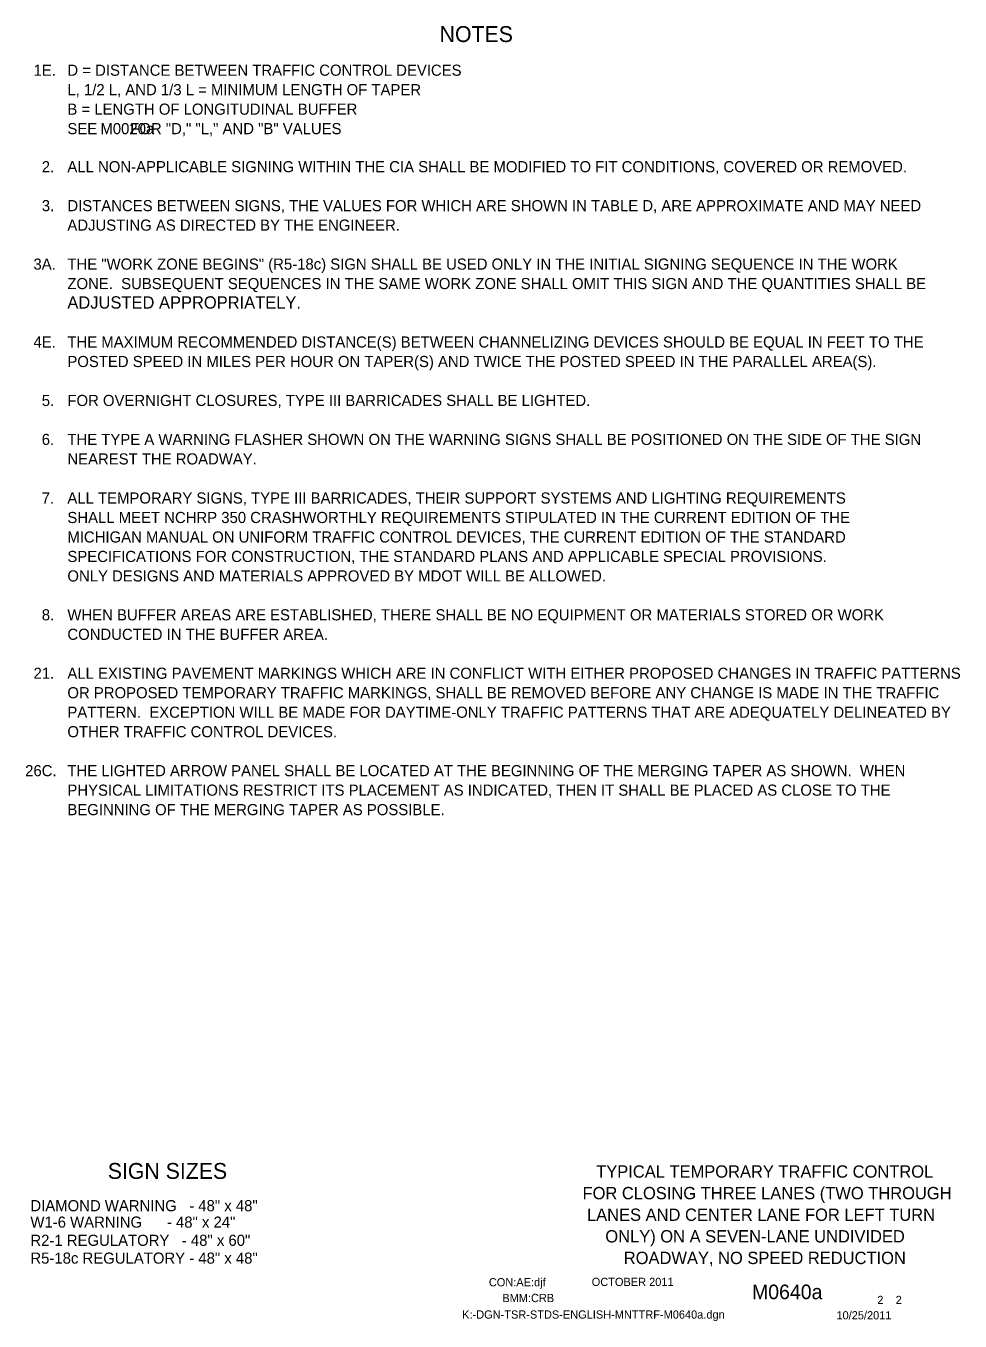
# Model space of a CAD drawing. Extents: x 16723 to 18475, y 7015 to 8267.
# Drawn here: x 17770 to 18475, y 7218 to 8195 of the extents above; entities that cross this region are included whole.
import ezdxf

# ---------------------------------------------------------------- set-up
doc = ezdxf.new("R2010")
doc.units = 0
for name, color, linetype in [('BORDER', 7, 'Continuous'), ('BORDER_SIGNAL_WO', 7, 'Continuous'), ('TYPICAL_TEXT_DIMEN_PR', 7, 'Continuous')]:
    doc.layers.add(name, color=color, linetype=linetype)

msp = doc.modelspace()

# ---------------------------------------------------------------- linework, layer by layer
at = {"layer": 'BORDER'}
msp.add_line((18318.25, 7297.5), (18318.25, 7297.5), dxfattribs=at)

# ---------------------------------------------------------------- texts
for s, p in [('TYPICAL TEMPORARY TRAFFIC CONTROL', (18200.67, 7326.32)), ('FOR CLOSING THREE LANES (TWO THROUGH', (18190.36, 7310.02)), ('LANES AND CENTER LANE FOR LEFT TURN', (18193.72, 7293.72)), ('ONLY) ON A SEVEN-LANE UNDIVIDED', (18207.56, 7277.42)), ('ROADWAY, NO SPEED REDUCTION', (18221.48, 7261.12))]:
    msp.add_text(s, height=9.3, dxfattribs=at).set_placement(p)
at = {"layer": 'BORDER_SIGNAL_WO'}
for s, height, p in [('CON:AE:djf', 6.2, (18119.69, 7244.31)), ('    OCTOBER 2011    ', 6.2, (18188.08, 7244.59)), ('    M0640a   ', 11, (18301.86, 7234.63)), ('BMM:CRB   ', 6.2, (18129.81, 7232.42)), (' 2    2 ', 6.2, (18410.45, 7230.95)), ('K:-DGN-TSR-STDS-ENGLISH-MNTTRF-M0640a.dgn         ', 6.2, (18099.55, 7219.96)), ('10/25/2011    ', 6.2, (18381.93, 7219.38))]:
    msp.add_text(s, height=height, dxfattribs=at).set_placement(p)
at = {"layer": 'TYPICAL_TEXT_DIMEN_PR'}
for s, height, p in [('NOTES', 12, (18082.55, 8183.25)), ('1E.', 8.4, (17776.19, 8157.81)), ('D = DISTANCE BETWEEN TRAFFIC CONTROL DEVICES', 8.4, (17801.7, 8157.81)), ('L, 1/2 L, AND 1/3 L = MINIMUM LENGTH OF TAPER', 8.4, (17801.7, 8143.11)), ('B = LENGTH OF LONGITUDINAL BUFFER', 8.4, (17801.7, 8128.41)), ('SEE        FOR "D," "L," AND "B" VALUES', 8.4, (17801.7, 8113.71)), ('M0020a', 8.4, (17826.62, 8113.71)), ('2.', 8.4, (17782.39, 8085)), ('ALL NON-APPLICABLE SIGNING WITHIN THE CIA SHALL BE MODIFIED TO FIT CONDITIONS, COVERED OR REMOVED.', 8.4, (17801.7, 8085)), ('3.', 8.4, (17782.39, 8055.6)), ('DISTANCES BETWEEN SIGNS, THE VALUES FOR WHICH ARE SHOWN IN TABLE D, ARE APPROXIMATE AND MAY NEED', 8.4, (17801.7, 8055.6)), ('ADJUSTING AS DIRECTED BY THE ENGINEER.', 8.4, (17801.7, 8040.9)), ('3A.', 8.4, (17776.09, 8011.5)), ('THE "WORK ZONE BEGINS" (R5-18c) SIGN SHALL BE USED ONLY IN THE INITIAL SIGNING SEQUENCE IN THE WORK', 8.4, (17801.7, 8011.5)), ('ZONE.  SUBSEQUENT SEQUENCES IN THE SAME WORK ZONE SHALL OMIT THIS SIGN AND THE QUANTITIES SHALL BE', 8.4, (17801.7, 7996.8)), ('ADJUSTED APPROPRIATELY.', 9.3, (17801.7, 7982.1)), ('4E.', 8.4, (17776.13, 7952.7)), ('THE MAXIMUM RECOMMENDED DISTANCE(S) BETWEEN CHANNELIZING DEVICES SHOULD BE EQUAL IN FEET TO THE', 8.4, (17801.7, 7952.7)), ('POSTED SPEED IN MILES PER HOUR ON TAPER(S) AND TWICE THE POSTED SPEED IN THE PARALLEL AREA(S).', 8.4, (17801.7, 7938)), ('5.', 8.4, (17782.39, 7908.6)), ('FOR OVERNIGHT CLOSURES, TYPE III BARRICADES SHALL BE LIGHTED.', 8.4, (17801.7, 7908.6)), ('6.', 8.4, (17782.34, 7879.2)), ('THE TYPE A WARNING FLASHER SHOWN ON THE WARNING SIGNS SHALL BE POSITIONED ON THE SIDE OF THE SIGN', 8.4, (17801.7, 7879.2)), ('NEAREST THE ROADWAY.', 8.4, (17801.7, 7864.5)), ('7.', 8.4, (17782.34, 7834.97)), ('ALL TEMPORARY SIGNS, TYPE III BARRICADES, THEIR SUPPORT SYSTEMS AND LIGHTING REQUIREMENTS', 8.4, (17801.7, 7834.99)), ('SHALL MEET NCHRP 350 CRASHWORTHLY REQUIREMENTS STIPULATED IN THE CURRENT EDITION OF THE', 8.4, (17801.7, 7820.29)), ('MICHIGAN MANUAL ON UNIFORM TRAFFIC CONTROL DEVICES, THE CURRENT EDITION OF THE STANDARD', 8.4, (17801.7, 7805.59)), ('SPECIFICATIONS FOR CONSTRUCTION, THE STANDARD PLANS AND APPLICABLE SPECIAL PROVISIONS.', 8.4, (17801.7, 7790.89)), ('ONLY DESIGNS AND MATERIALS APPROVED BY MDOT WILL BE ALLOWED.', 8.4, (17801.7, 7776.19)), ('8.', 8.4, (17782.39, 7746.85)), ('WHEN BUFFER AREAS ARE ESTABLISHED, THERE SHALL BE NO EQUIPMENT OR MATERIALS STORED OR WORK     ', 8.4, (17801.7, 7746.85)), ('CONDUCTED IN THE BUFFER AREA.', 8.4, (17801.7, 7732.15)), ('21.', 8.4, (17776.14, 7702.75)), ('ALL EXISTING PAVEMENT MARKINGS WHICH ARE IN CONFLICT WITH EITHER PROPOSED CHANGES IN TRAFFIC PATTERNS', 8.4, (17801.7, 7702.75)), ('OR PROPOSED TEMPORARY TRAFFIC MARKINGS, SHALL BE REMOVED BEFORE ANY CHANGE IS MADE IN THE TRAFFIC', 8.4, (17801.7, 7688.05)), ('PATTERN.  EXCEPTION WILL BE MADE FOR DAYTIME-ONLY TRAFFIC PATTERNS THAT ARE ADEQUATELY DELINEATED BY', 8.4, (17801.7, 7673.35)), ('OTHER TRAFFIC CONTROL DEVICES.', 8.4, (17801.7, 7658.65)), ('26C.', 8.4, (17769.83, 7629.25)), ('THE LIGHTED ARROW PANEL SHALL BE LOCATED AT THE BEGINNING OF THE MERGING TAPER AS SHOWN.  WHEN', 8.4, (17801.7, 7629.25)), ('PHYSICAL LIMITATIONS RESTRICT ITS PLACEMENT AS INDICATED, THEN IT SHALL BE PLACED AS CLOSE TO THE', 8.4, (17801.7, 7614.55)), ('BEGINNING OF THE MERGING TAPER AS POSSIBLE.', 8.4, (17801.7, 7599.85)), ('SIGN SIZES', 12, (17832.17, 7325.39)), ('DIAMOND WARNING   - 48" x 48"', 8.4, (17773.79, 7300.99)), ('W1-6 WARNING      - 48" x 24"', 8.4, (17773.79, 7288.59)), ('R2-1 REGULATORY   - 48" x 60"', 8.4, (17773.79, 7274.86)), ('R5-18c REGULATORY - 48" x 48"', 8.4, (17773.79, 7261.41))]:
    msp.add_text(s, height=height, dxfattribs=at).set_placement(p)

doc.saveas('drawing.dxf')
